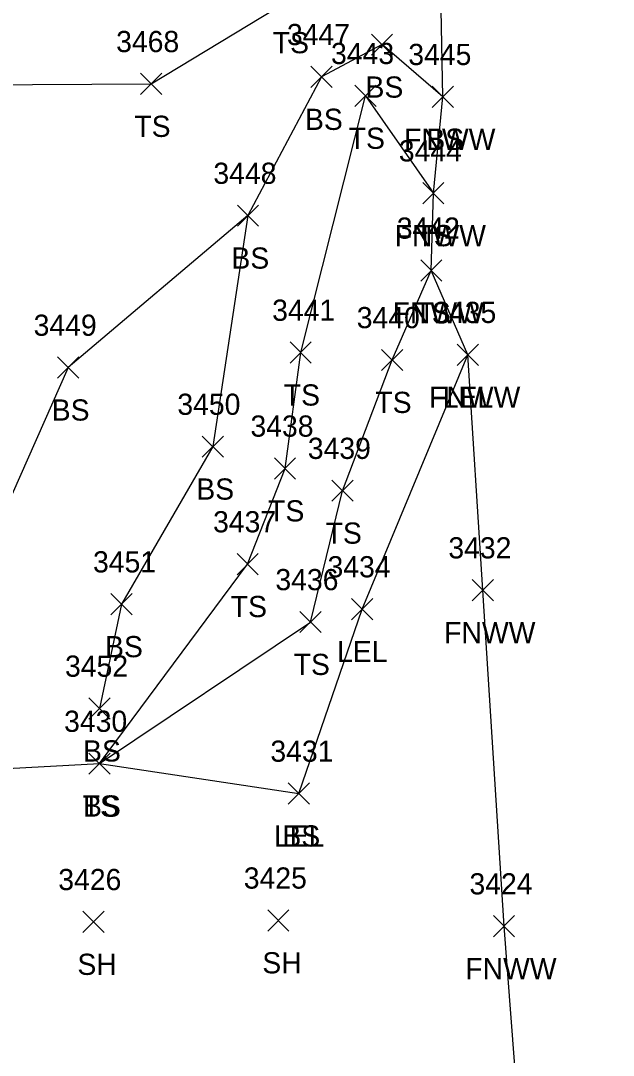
# Model space of a CAD drawing. Extents: x 1650221 to 1650634, y 244606 to 249996.
# Drawn here: x 1650420.5 to 1650476.4, y 246721.6 to 246819.2 of the extents above; entities that cross this region are included whole.
import ezdxf

# ---------------------------------------------------------------- set-up
doc = ezdxf.new("R2010")
doc.units = 0
for name, color, linetype in [('L_A', 7, 'Continuous'), ('L_I', 7, 'Continuous'), ('L_TIC', 7, 'Continuous'), ('LARO', 7, 'Continuous'), ('LELB', 7, 'Continuous'), ('LFNC', 7, 'Continuous'), ('LSOGP', 7, 'Continuous')]:
    doc.layers.add(name, color=color, linetype=linetype)

msp = doc.modelspace()

# ---------------------------------------------------------------- linework, layer by layer
at = {"layer": 'L_TIC'}
for points in [[(1650453.55, 246815.975), (1650455.55, 246817.975)], [(1650455.55, 246815.975), (1650453.55, 246817.975)], [(1650447.838, 246812.931), (1650449.838, 246814.931)], [(1650449.838, 246812.931), (1650447.838, 246814.931)], [(1650431.774, 246812.271), (1650433.774, 246814.271)], [(1650433.774, 246812.271), (1650431.774, 246814.271)], [(1650451.998, 246811.146), (1650453.998, 246813.146)], [(1650453.998, 246811.146), (1650451.998, 246813.146)], [(1650459.288, 246811.051), (1650461.288, 246813.051)], [(1650461.288, 246811.051), (1650459.288, 246813.051)], [(1650459.288, 246811.051), (1650461.288, 246813.051)], [(1650461.288, 246811.051), (1650459.288, 246813.051)], [(1650458.394, 246801.956), (1650460.394, 246803.956)], [(1650460.394, 246801.956), (1650458.394, 246803.956)], [(1650458.394, 246801.956), (1650460.394, 246803.956)], [(1650460.394, 246801.956), (1650458.394, 246803.956)], [(1650440.902, 246799.841), (1650442.902, 246801.841)], [(1650442.902, 246799.841), (1650440.902, 246801.841)], [(1650440.902, 246799.841), (1650442.902, 246801.841)], [(1650442.902, 246799.841), (1650440.902, 246801.841)], [(1650458.197, 246794.668), (1650460.197, 246796.668)], [(1650460.197, 246794.668), (1650458.197, 246796.668)], [(1650458.197, 246794.668), (1650460.197, 246796.668)], [(1650460.197, 246794.668), (1650458.197, 246796.668)], [(1650445.876, 246786.921), (1650447.876, 246788.921)], [(1650447.876, 246786.921), (1650445.876, 246788.921)], [(1650461.639, 246786.714), (1650463.639, 246788.714)], [(1650463.639, 246786.714), (1650461.639, 246788.714)], [(1650461.639, 246786.714), (1650463.639, 246788.714)], [(1650463.639, 246786.714), (1650461.639, 246788.714)], [(1650454.51, 246786.223), (1650456.51, 246788.223)], [(1650456.51, 246786.223), (1650454.51, 246788.223)], [(1650423.95, 246785.506), (1650425.95, 246787.506)], [(1650425.95, 246785.506), (1650423.95, 246787.506)], [(1650437.587, 246778.047), (1650439.587, 246780.047)], [(1650439.587, 246778.047), (1650437.587, 246780.047)], [(1650444.398, 246775.989), (1650446.398, 246777.989)], [(1650446.398, 246775.989), (1650444.398, 246777.989)], [(1650449.817, 246773.888), (1650451.817, 246775.888)], [(1650451.817, 246773.888), (1650449.817, 246775.888)], [(1650440.87, 246766.961), (1650442.87, 246768.961)], [(1650442.87, 246766.961), (1650440.87, 246768.961)], [(1650463.066, 246764.501), (1650465.066, 246766.501)], [(1650465.066, 246764.501), (1650463.066, 246766.501)], [(1650428.979, 246763.178), (1650430.979, 246765.178)], [(1650430.979, 246763.178), (1650428.979, 246765.178)], [(1650451.668, 246762.716), (1650453.668, 246764.716)], [(1650453.668, 246762.716), (1650451.668, 246764.716)], [(1650446.805, 246761.502), (1650448.805, 246763.502)], [(1650448.805, 246761.502), (1650446.805, 246763.502)], [(1650426.903, 246753.337), (1650428.903, 246755.337)], [(1650428.903, 246753.337), (1650426.903, 246755.337)], [(1650426.903, 246748.136), (1650428.903, 246750.136)], [(1650428.903, 246748.136), (1650426.903, 246750.136)], [(1650426.903, 246748.136), (1650428.903, 246750.136)], [(1650428.903, 246748.136), (1650426.903, 246750.136)], [(1650426.903, 246748.136), (1650428.903, 246750.136)], [(1650428.903, 246748.136), (1650426.903, 246750.136)], [(1650445.71, 246745.315), (1650447.71, 246747.315)], [(1650447.71, 246745.315), (1650445.71, 246747.315)], [(1650445.71, 246745.315), (1650447.71, 246747.315)], [(1650447.71, 246745.315), (1650445.71, 246747.315)], [(1650426.323, 246733.204), (1650428.323, 246735.204)], [(1650428.323, 246733.204), (1650426.323, 246735.204)], [(1650443.768, 246733.346), (1650445.768, 246735.346)], [(1650445.768, 246733.346), (1650443.768, 246735.346)], [(1650465.058, 246732.799), (1650467.058, 246734.799)], [(1650467.058, 246732.799), (1650465.058, 246734.799)]]:
    msp.add_lwpolyline(points, dxfattribs=at)
at = {"layer": 'LARO'}
msp.add_lwpolyline([(1650446.71, 246746.315), (1650452.668, 246763.716), (1650462.639, 246787.714)], dxfattribs=at)
at = {"layer": 'LELB'}
for points in [[(1650397.679, 246807.368), (1650415.942, 246813.191), (1650432.774, 246813.271), (1650445.833, 246821.166), (1650460.046, 246825.274)], [(1650460.288, 246812.051), (1650454.55, 246816.975), (1650448.838, 246813.931), (1650441.902, 246800.841), (1650438.587, 246779.047), (1650429.979, 246764.178), (1650427.903, 246754.337)], [(1650427.903, 246749.136), (1650441.87, 246767.961), (1650445.398, 246776.989), (1650446.876, 246787.921), (1650452.998, 246812.146), (1650459.394, 246802.956)], [(1650441.902, 246800.841), (1650424.95, 246786.506), (1650416.568, 246767.686), (1650404.546, 246760.548), (1650399.824, 246757.067)], [(1650415.884, 246671.758), (1650408.611, 246692.745), (1650408.273, 246732.321), (1650411.062, 246748.25), (1650427.903, 246749.136), (1650447.805, 246762.502), (1650450.817, 246774.888), (1650455.51, 246787.223), (1650459.197, 246795.668)], [(1650427.903, 246749.136), (1650446.71, 246746.315)]]:
    msp.add_lwpolyline(points, dxfattribs=at)
at = {"layer": 'LFNC'}
msp.add_lwpolyline([(1650476.368, 246602.099), (1650473.826, 246635.822), (1650472.861, 246649.811), (1650470.876, 246672.082), (1650469.071, 246696.986), (1650467.717, 246712.4), (1650466.058, 246733.799), (1650464.066, 246765.501), (1650462.639, 246787.714), (1650459.197, 246795.668), (1650459.394, 246802.956), (1650460.288, 246812.051), (1650460.046, 246825.274)], dxfattribs=at)
at = {"layer": 'LSOGP'}
msp.add_lwpolyline([(1650476.368, 246602.099), (1650473.826, 246635.822), (1650472.861, 246649.811), (1650470.876, 246672.082), (1650469.071, 246696.986), (1650467.717, 246712.4), (1650466.058, 246733.799), (1650464.066, 246765.501), (1650462.639, 246787.714), (1650459.197, 246795.668), (1650459.394, 246802.956), (1650460.288, 246812.051), (1650460.046, 246825.274)], dxfattribs=at)

# ---------------------------------------------------------------- texts
at = {"layer": 'L_A'}
for s, p in [('TS', (1650444.242, 246816.166)), ('BS', (1650452.991, 246811.975)), ('TS', (1650431.183, 246808.271)), ('BS', (1650447.279, 246808.931)), ('TS', (1650451.407, 246807.146)), ('BS', (1650458.729, 246807.051)), ('FNWW', (1650456.634, 246807.051)), ('FNWW', (1650455.741, 246797.956)), ('TS', (1650457.804, 246797.956)), ('BS', (1650440.343, 246795.841)), ('BS', (1650440.343, 246795.841)), ('FNWW', (1650455.544, 246790.668)), ('TS', (1650457.607, 246790.668)), ('TS', (1650445.285, 246782.921)), ('FNWW', (1650458.985, 246782.714)), ('LEL', (1650460.277, 246782.714)), ('TS', (1650453.92, 246782.223)), ('BS', (1650423.391, 246781.506)), ('BS', (1650437.028, 246774.047)), ('TS', (1650443.807, 246771.989)), ('TS', (1650449.226, 246769.888)), ('TS', (1650440.279, 246762.961)), ('FNWW', (1650460.412, 246760.501)), ('BS', (1650428.42, 246759.178)), ('LEL', (1650450.306, 246758.716)), ('TS', (1650446.214, 246757.502)), ('BS', (1650426.344, 246749.337)), ('TS', (1650426.313, 246744.136)), ('TS', (1650426.313, 246744.136)), ('BS', (1650426.344, 246744.136)), ('LEL', (1650444.347, 246741.315)), ('BS', (1650445.151, 246741.315)), ('SH', (1650425.811, 246729.204)), ('SH', (1650443.256, 246729.346)), ('FNWW', (1650462.404, 246728.799))]:
    msp.add_text(s, height=2, dxfattribs=at).set_placement(p)
at = {"layer": 'L_I'}
for s, p in [('3447', (1650445.578, 246816.931)), ('3468', (1650429.467, 246816.271)), ('3443', (1650449.738, 246815.146)), ('3445', (1650457.028, 246815.051)), ('3445', (1650457.028, 246815.051)), ('3444', (1650456.135, 246805.956)), ('3444', (1650456.135, 246805.956)), ('3448', (1650438.642, 246803.841)), ('3448', (1650438.642, 246803.841)), ('3442', (1650455.938, 246798.668)), ('3442', (1650455.938, 246798.668)), ('3441', (1650444.183, 246790.921)), ('3435', (1650459.379, 246790.714)), ('3435', (1650459.379, 246790.714)), ('3449', (1650421.683, 246789.506)), ('3440', (1650452.164, 246790.223)), ('3450', (1650435.241, 246782.047)), ('3438', (1650442.138, 246779.989)), ('3439', (1650447.549, 246777.888)), ('3437', (1650438.61, 246770.961)), ('3432', (1650460.806, 246768.501)), ('3451', (1650427.286, 246767.178)), ('3434', (1650449.408, 246766.716)), ('3436', (1650444.49, 246765.502)), ('3452', (1650424.643, 246757.337)), ('3430', (1650424.557, 246752.136)), ('3430', (1650424.557, 246752.136)), ('3430', (1650424.557, 246752.136)), ('3431', (1650444.017, 246749.315)), ('3431', (1650444.017, 246749.315)), ('3426', (1650424.008, 246737.204)), ('3425', (1650441.508, 246737.346)), ('3424', (1650462.798, 246736.799))]:
    msp.add_text(s, height=2, dxfattribs=at).set_placement(p)

doc.saveas('drawing.dxf')
